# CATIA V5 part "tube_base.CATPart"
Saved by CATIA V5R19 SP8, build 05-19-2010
Part number: tube_base
Bounding box of the stored display mesh (mm): x 0 to 1500, y -20 to 20, z -20 to 20
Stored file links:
  U:\Thinkmotion\Assemblage final\tube_base.CATPart
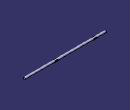
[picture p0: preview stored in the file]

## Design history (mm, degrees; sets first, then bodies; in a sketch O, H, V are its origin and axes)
Body1 (main body)
  Sketch1 on yz-plane, origin (0, 0, 0), H (0, 1, 0), V (0, 0, 1)
    circle A1 centre (0, 0) radius 20
    radius A1 = 20
  Pad1: profile Sketch1, direction (1, 0, 0), length 1500
  Sketch2 on xy-plane, origin (0, 0, 0), H (1, 0, 0), V (0, 1, 0)
    line L1 (900, 55) -> (945, 55)
    line L2 (945, 55) -> (945, 15)
    line L3 (945, 15) -> (900, 15)
    line L4 (900, 15) -> (900, 55)
    reference projected line E1 through (0, 0) direction (1, 0) from axis of face of Pad1 from Sketch1.A1
    distance L3 E1 = 15
    length L4 = 40
    length L1 = 45
    distance L4 V = 900
    horizontal: L1 H, L3 H
    vertical: L2 V, L4 V
  Pocket1: profile Sketch2, direction (0, 0, -1), length 1500, mirrored extent
  Mirror1: of Pocket1, Sketch2, about zx-plane
  Sketch3 on face of Pocket1 from Sketch2.L3, origin (0, 15, 0), H (-1, 0, 0), V (0, 0, 1)
    line L1 (-230, -13.2288) -> (-180, -13.2288)
    line L2 (-180, -13.2288) -> (-180, 13.2288)
    line L3 (-180, 13.2288) -> (-230, 13.2288)
    line L4 (-230, 13.2288) -> (-230, -13.2288)
    reference projected line E1 (-945, 13.2288) -> (-900, 13.2288) from edge [face of Pocket1 from Sketch2.L3 | face of Pad1 from Sketch1.A1]
    reference projected line E2 (-945, -13.2288) -> (-900, -13.2288) from edge [face of Pad1 from Sketch1.A1 | face of Pocket1 from Sketch2.L3]
    length L3 = 50
    horizontal: L1 H, L3 H
    vertical: L2 V, L4 V
    coincidence: L3 E1, E2 L1
  Pocket2: profile Sketch3, direction (0, 1, 0), length 1500
  Mirror2: of Pocket2, Sketch3, about zx-plane
  Sketch4 on start face of Pocket2, origin (210.1707, 15, -2.7361), H (1, 0, 0), V (0, 0, -1)
    point P1 (-5.1707, -2.7361)
    reference intersected line E1 through (0, -2.7361) direction (1, 0) from xy-plane
    reference projected line E2 (-30.1707, -15.9648) -> (-30.1707, 10.4927) from edge [face of Pocket2 from Sketch3.L2 | face of Pad1 from Sketch1.A1]
    distance P1 E2 = 25
    coincidence: P1 E1
  Hole1: placed by Sketch4, at (205, 15, 0) direction (0, -1, 0), diameter 20, through (limit type 3)
  Sketch5 on face of Pocket1 from Sketch2.L3, origin (922.9516, 15, -0.2655), H (1, 0, 0), V (0, 0, -1)
    point P1 (2.0484, -0.2655)
    reference intersected line E1 through (0, -0.2655) direction (1, 0) from xy-plane
    reference projected line E2 (-22.9516, 12.9632) -> (-22.9516, -13.4943) from edge [face of Pad1 from Sketch1.A1 | face of Pocket1 from Sketch2.L4]
    distance P1 E2 = 25
    coincidence: P1 E1
  Hole2: placed by Sketch5, at (925, 15, 0) direction (0, -1, 0), diameter 20, through (limit type 3)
